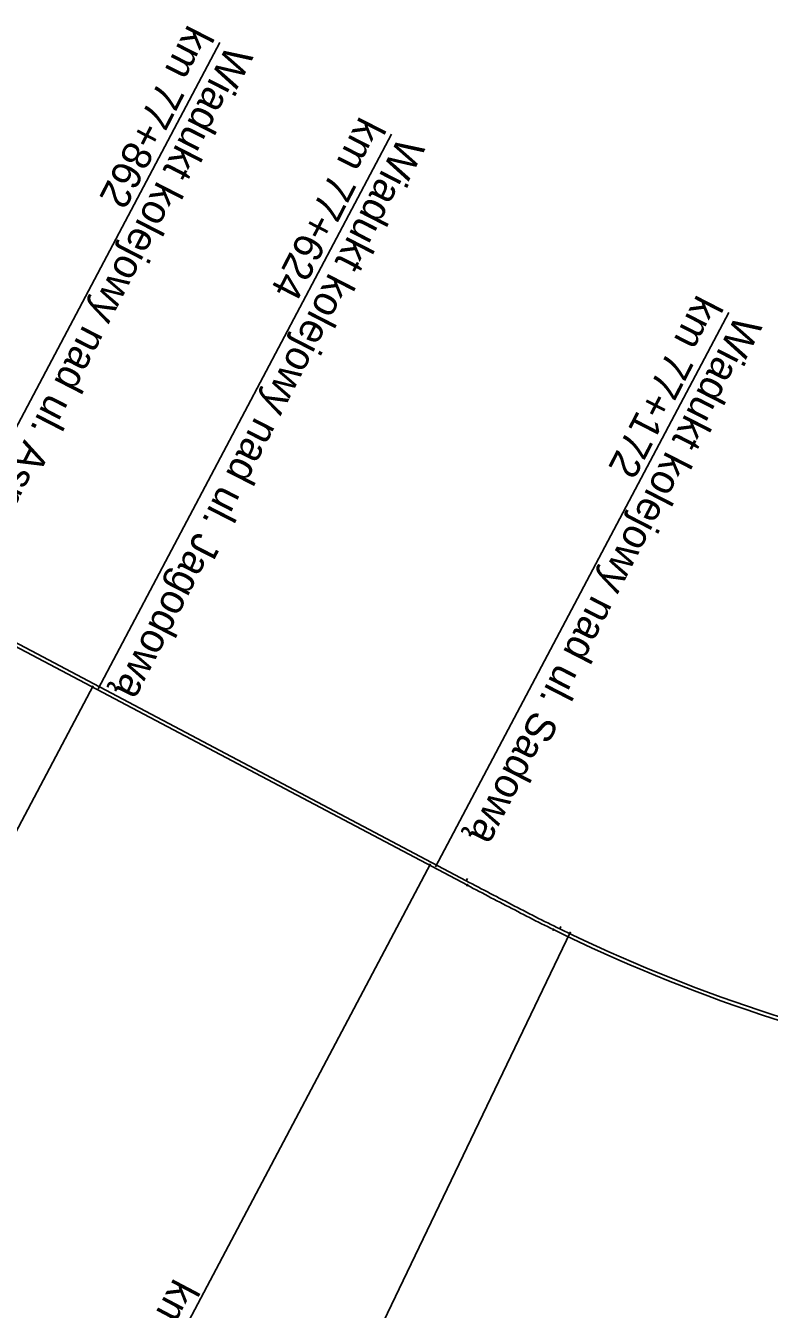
# Model space of a CAD drawing. Extents: x 6540402 to 6566579, y 5525343 to 5532423.
# Drawn here: x 6542041 to 6542924, y 5526352 to 5527877 of the extents above; entities that cross this region are included whole.
import ezdxf

# ---------------------------------------------------------------- set-up
doc = ezdxf.new("R2010")
doc.units = 0
for name, color, linetype in [('IR_ps_geometria', 7, 'Continuous'), ('TOR_PS_OPIS_T-hektometry projektowane', 7, 'Continuous'), ('TOR_PS_OPIS_T-opisy dodatkowe', 7, 'Continuous'), ('TOR_PS_OPIS_T-symbole geometrii', 7, 'Continuous'), ('TOR_PS_T-tory projektowane', 7, 'Continuous')]:
    doc.layers.add(name, color=color, linetype=linetype)

msp = doc.modelspace()

# ---------------------------------------------------------------- linework, layer by layer
at = {"layer": 'IR_ps_geometria'}
for points in [[(6542565.7, 5526856), (6542565.6, 5526855.8), (6542565.6, 5526855.8), (6542565.6, 5526855.8), (6542565.6, 5526855.8), (6542565.7, 5526855.7), (6542565.7, 5526855.7), (6542565.7, 5526855.7), (6542565.7, 5526855.6), (6542565.7, 5526855.6), (6542565.7, 5526855.6), (6542565.7, 5526855.5), (6542565.7, 5526855.5), (6542565.7, 5526855.5), (6542565.6, 5526855.5), (6542565.6, 5526855.4), (6542565.6, 5526855.4), (6542565.6, 5526855.4), (6542565.5, 5526855.4), (6542565.5, 5526855.4), (6542565.5, 5526855.4), (6542565.5, 5526855.4), (6542565.4, 5526855.4), (6542565.4, 5526855.4), (6542565.4, 5526855.4), (6542565.3, 5526855.4), (6542565.3, 5526855.4), (6542565.3, 5526855.4), (6542565.2, 5526855.4), (6542565.2, 5526855.5), (6542565.2, 5526855.5), (6542565.2, 5526855.5), (6542565.2, 5526855.6), (6542565.2, 5526855.6), (6542565.2, 5526855.6), (6542565.2, 5526855.7), (6542565.2, 5526855.7), (6542565.2, 5526855.7), (6542565.2, 5526855.7), (6542565.3, 5526855.8), (6542565.3, 5526855.8), (6542565.3, 5526855.8), (6542565.3, 5526855.8), (6542565.4, 5526855.8), (6542565.4, 5526855.8), (6542565.4, 5526855.9), (6542565.5, 5526855.9), (6542565.5, 5526855.8), (6542565.5, 5526855.8), (6542565.6, 5526855.8), (6542565.8, 5526856.3), (6542565.8, 5526856.3), (6542565.7, 5526856.3), (6542565.7, 5526856.3), (6542565.7, 5526856.4), (6542565.7, 5526856.4), (6542565.7, 5526856.4), (6542565.7, 5526856.4), (6542565.7, 5526856.5), (6542565.7, 5526856.5), (6542565.7, 5526856.5), (6542565.7, 5526856.6), (6542565.7, 5526856.6), (6542565.7, 5526856.6), (6542565.7, 5526856.7), (6542565.7, 5526856.7), (6542565.8, 5526856.7), (6542565.8, 5526856.7), (6542565.8, 5526856.7), (6542565.9, 5526856.7), (6542565.9, 5526856.7), (6542565.9, 5526856.7), (6542566, 5526856.7), (6542566, 5526856.7), (6542566, 5526856.7), (6542566.1, 5526856.7), (6542566.1, 5526856.7), (6542566.1, 5526856.6), (6542566.1, 5526856.6), (6542566.1, 5526856.6), (6542566.1, 5526856.6), (6542566.2, 5526856.5), (6542566.2, 5526856.5), (6542566.2, 5526856.5), (6542566.2, 5526856.4), (6542566.1, 5526856.4), (6542566.1, 5526856.4), (6542566.1, 5526856.3), (6542566.1, 5526856.3), (6542566.1, 5526856.3), (6542566, 5526856.3), (6542566, 5526856.3), (6542566, 5526856.2), (6542566, 5526856.2), (6542565.9, 5526856.2), (6542565.9, 5526856.2), (6542565.9, 5526856.2), (6542565.8, 5526856.3), (6542565.8, 5526856.3)], [(6542565.7, 5526856), (6542565.6, 5526855.8), (6542565.6, 5526855.8), (6542565.6, 5526855.8), (6542565.6, 5526855.8), (6542565.7, 5526855.7), (6542565.7, 5526855.7), (6542565.7, 5526855.7), (6542565.7, 5526855.6), (6542565.7, 5526855.6), (6542565.7, 5526855.6), (6542565.7, 5526855.5), (6542565.7, 5526855.5), (6542565.7, 5526855.5), (6542565.6, 5526855.5), (6542565.6, 5526855.4), (6542565.6, 5526855.4), (6542565.6, 5526855.4), (6542565.5, 5526855.4), (6542565.5, 5526855.4), (6542565.5, 5526855.4), (6542565.5, 5526855.4), (6542565.4, 5526855.4), (6542565.4, 5526855.4), (6542565.4, 5526855.4), (6542565.3, 5526855.4), (6542565.3, 5526855.4), (6542565.3, 5526855.4), (6542565.2, 5526855.4), (6542565.2, 5526855.5), (6542565.2, 5526855.5), (6542565.2, 5526855.5), (6542565.2, 5526855.6), (6542565.2, 5526855.6), (6542565.2, 5526855.6), (6542565.2, 5526855.7), (6542565.2, 5526855.7), (6542565.2, 5526855.7), (6542565.2, 5526855.7), (6542565.3, 5526855.8), (6542565.3, 5526855.8), (6542565.3, 5526855.8), (6542565.3, 5526855.8), (6542565.4, 5526855.8), (6542565.4, 5526855.8), (6542565.4, 5526855.9), (6542565.5, 5526855.9), (6542565.5, 5526855.8), (6542565.5, 5526855.8), (6542565.6, 5526855.8), (6542565.8, 5526856.3), (6542565.8, 5526856.3), (6542565.7, 5526856.3), (6542565.7, 5526856.3), (6542565.7, 5526856.4), (6542565.7, 5526856.4), (6542565.7, 5526856.4), (6542565.7, 5526856.4), (6542565.7, 5526856.5), (6542565.7, 5526856.5), (6542565.7, 5526856.5), (6542565.7, 5526856.6), (6542565.7, 5526856.6), (6542565.7, 5526856.6), (6542565.7, 5526856.7), (6542565.7, 5526856.7), (6542565.8, 5526856.7), (6542565.8, 5526856.7), (6542565.8, 5526856.7), (6542565.9, 5526856.7), (6542565.9, 5526856.7), (6542565.9, 5526856.7), (6542566, 5526856.7), (6542566, 5526856.7), (6542566, 5526856.7), (6542566.1, 5526856.7), (6542566.1, 5526856.7), (6542566.1, 5526856.6), (6542566.1, 5526856.6), (6542566.1, 5526856.6), (6542566.1, 5526856.6), (6542566.2, 5526856.5), (6542566.2, 5526856.5), (6542566.2, 5526856.5), (6542566.2, 5526856.4), (6542566.1, 5526856.4), (6542566.1, 5526856.4), (6542566.1, 5526856.3), (6542566.1, 5526856.3), (6542566.1, 5526856.3), (6542566, 5526856.3), (6542566, 5526856.3), (6542566, 5526856.2), (6542566, 5526856.2), (6542565.9, 5526856.2), (6542565.9, 5526856.2), (6542565.9, 5526856.2), (6542565.8, 5526856.3), (6542565.8, 5526856.3)], [(6542565.7, 5526856), (6542565.6, 5526855.8), (6542565.6, 5526855.8), (6542565.6, 5526855.8), (6542565.6, 5526855.8), (6542565.7, 5526855.7), (6542565.7, 5526855.7), (6542565.7, 5526855.7), (6542565.7, 5526855.6), (6542565.7, 5526855.6), (6542565.7, 5526855.6), (6542565.7, 5526855.5), (6542565.7, 5526855.5), (6542565.7, 5526855.5), (6542565.6, 5526855.5), (6542565.6, 5526855.4), (6542565.6, 5526855.4), (6542565.6, 5526855.4), (6542565.5, 5526855.4), (6542565.5, 5526855.4), (6542565.5, 5526855.4), (6542565.5, 5526855.4), (6542565.4, 5526855.4), (6542565.4, 5526855.4), (6542565.4, 5526855.4), (6542565.3, 5526855.4), (6542565.3, 5526855.4), (6542565.3, 5526855.4), (6542565.2, 5526855.4), (6542565.2, 5526855.5), (6542565.2, 5526855.5), (6542565.2, 5526855.5), (6542565.2, 5526855.6), (6542565.2, 5526855.6), (6542565.2, 5526855.6), (6542565.2, 5526855.7), (6542565.2, 5526855.7), (6542565.2, 5526855.7), (6542565.2, 5526855.7), (6542565.3, 5526855.8), (6542565.3, 5526855.8), (6542565.3, 5526855.8), (6542565.3, 5526855.8), (6542565.4, 5526855.8), (6542565.4, 5526855.8), (6542565.4, 5526855.9), (6542565.5, 5526855.9), (6542565.5, 5526855.8), (6542565.5, 5526855.8), (6542565.6, 5526855.8), (6542565.8, 5526856.3), (6542565.8, 5526856.3), (6542565.7, 5526856.3), (6542565.7, 5526856.3), (6542565.7, 5526856.4), (6542565.7, 5526856.4), (6542565.7, 5526856.4), (6542565.7, 5526856.4), (6542565.7, 5526856.5), (6542565.7, 5526856.5), (6542565.7, 5526856.5), (6542565.7, 5526856.6), (6542565.7, 5526856.6), (6542565.7, 5526856.6), (6542565.7, 5526856.7), (6542565.7, 5526856.7), (6542565.8, 5526856.7), (6542565.8, 5526856.7), (6542565.8, 5526856.7), (6542565.9, 5526856.7), (6542565.9, 5526856.7), (6542565.9, 5526856.7), (6542566, 5526856.7), (6542566, 5526856.7), (6542566, 5526856.7), (6542566.1, 5526856.7), (6542566.1, 5526856.7), (6542566.1, 5526856.6), (6542566.1, 5526856.6), (6542566.1, 5526856.6), (6542566.1, 5526856.6), (6542566.2, 5526856.5), (6542566.2, 5526856.5), (6542566.2, 5526856.5), (6542566.2, 5526856.4), (6542566.1, 5526856.4), (6542566.1, 5526856.4), (6542566.1, 5526856.3), (6542566.1, 5526856.3), (6542566.1, 5526856.3), (6542566, 5526856.3), (6542566, 5526856.3), (6542566, 5526856.2), (6542566, 5526856.2), (6542565.9, 5526856.2), (6542565.9, 5526856.2), (6542565.9, 5526856.2), (6542565.8, 5526856.3), (6542565.8, 5526856.3)], [(6542565.7, 5526856), (6542565.6, 5526855.8), (6542565.6, 5526855.8), (6542565.6, 5526855.8), (6542565.6, 5526855.8), (6542565.7, 5526855.7), (6542565.7, 5526855.7), (6542565.7, 5526855.7), (6542565.7, 5526855.6), (6542565.7, 5526855.6), (6542565.7, 5526855.6), (6542565.7, 5526855.5), (6542565.7, 5526855.5), (6542565.7, 5526855.5), (6542565.6, 5526855.5), (6542565.6, 5526855.4), (6542565.6, 5526855.4), (6542565.6, 5526855.4), (6542565.5, 5526855.4), (6542565.5, 5526855.4), (6542565.5, 5526855.4), (6542565.5, 5526855.4), (6542565.4, 5526855.4), (6542565.4, 5526855.4), (6542565.4, 5526855.4), (6542565.3, 5526855.4), (6542565.3, 5526855.4), (6542565.3, 5526855.4), (6542565.2, 5526855.4), (6542565.2, 5526855.5), (6542565.2, 5526855.5), (6542565.2, 5526855.5), (6542565.2, 5526855.6), (6542565.2, 5526855.6), (6542565.2, 5526855.6), (6542565.2, 5526855.7), (6542565.2, 5526855.7), (6542565.2, 5526855.7), (6542565.2, 5526855.7), (6542565.3, 5526855.8), (6542565.3, 5526855.8), (6542565.3, 5526855.8), (6542565.3, 5526855.8), (6542565.4, 5526855.8), (6542565.4, 5526855.8), (6542565.4, 5526855.9), (6542565.5, 5526855.9), (6542565.5, 5526855.8), (6542565.5, 5526855.8), (6542565.6, 5526855.8), (6542565.8, 5526856.3), (6542565.8, 5526856.3), (6542565.7, 5526856.3), (6542565.7, 5526856.3), (6542565.7, 5526856.4), (6542565.7, 5526856.4), (6542565.7, 5526856.4), (6542565.7, 5526856.4), (6542565.7, 5526856.5), (6542565.7, 5526856.5), (6542565.7, 5526856.5), (6542565.7, 5526856.6), (6542565.7, 5526856.6), (6542565.7, 5526856.6), (6542565.7, 5526856.7), (6542565.7, 5526856.7), (6542565.8, 5526856.7), (6542565.8, 5526856.7), (6542565.8, 5526856.7), (6542565.9, 5526856.7), (6542565.9, 5526856.7), (6542565.9, 5526856.7), (6542566, 5526856.7), (6542566, 5526856.7), (6542566, 5526856.7), (6542566.1, 5526856.7), (6542566.1, 5526856.7), (6542566.1, 5526856.6), (6542566.1, 5526856.6), (6542566.1, 5526856.6), (6542566.1, 5526856.6), (6542566.2, 5526856.5), (6542566.2, 5526856.5), (6542566.2, 5526856.5), (6542566.2, 5526856.4), (6542566.1, 5526856.4), (6542566.1, 5526856.4), (6542566.1, 5526856.3), (6542566.1, 5526856.3), (6542566.1, 5526856.3), (6542566, 5526856.3), (6542566, 5526856.3), (6542566, 5526856.2), (6542566, 5526856.2), (6542565.9, 5526856.2), (6542565.9, 5526856.2), (6542565.9, 5526856.2), (6542565.8, 5526856.3), (6542565.8, 5526856.3)], [(6542667.9, 5526803.3), (6542667.7, 5526803.1), (6542667.8, 5526803), (6542667.8, 5526803), (6542667.8, 5526803), (6542667.8, 5526803), (6542667.9, 5526803), (6542667.9, 5526802.9), (6542667.9, 5526802.9), (6542667.9, 5526802.9), (6542667.9, 5526802.8), (6542667.9, 5526802.8), (6542667.9, 5526802.8), (6542667.9, 5526802.7), (6542667.8, 5526802.7), (6542667.8, 5526802.7), (6542667.8, 5526802.7), (6542667.8, 5526802.6), (6542667.7, 5526802.6), (6542667.7, 5526802.6), (6542667.7, 5526802.6), (6542667.7, 5526802.6), (6542667.6, 5526802.6), (6542667.6, 5526802.6), (6542667.6, 5526802.6), (6542667.5, 5526802.6), (6542667.5, 5526802.6), (6542667.5, 5526802.7), (6542667.4, 5526802.7), (6542667.4, 5526802.7), (6542667.4, 5526802.7), (6542667.4, 5526802.8), (6542667.4, 5526802.8), (6542667.4, 5526802.8), (6542667.4, 5526802.9), (6542667.4, 5526802.9), (6542667.4, 5526802.9), (6542667.4, 5526803), (6542667.4, 5526803), (6542667.4, 5526803), (6542667.5, 5526803), (6542667.5, 5526803), (6542667.5, 5526803.1), (6542667.6, 5526803.1), (6542667.6, 5526803.1), (6542667.6, 5526803.1), (6542667.7, 5526803.1), (6542667.7, 5526803.1), (6542667.7, 5526803.1), (6542667.7, 5526803.1), (6542668, 5526803.5), (6542667.9, 5526803.5), (6542667.9, 5526803.6), (6542667.9, 5526803.6), (6542667.9, 5526803.6), (6542667.9, 5526803.6), (6542667.8, 5526803.7), (6542667.8, 5526803.7), (6542667.8, 5526803.7), (6542667.8, 5526803.8), (6542667.8, 5526803.8), (6542667.8, 5526803.8), (6542667.9, 5526803.8), (6542667.9, 5526803.9), (6542667.9, 5526803.9), (6542667.9, 5526803.9), (6542667.9, 5526803.9), (6542668, 5526804), (6542668, 5526804), (6542668, 5526804), (6542668.1, 5526804), (6542668.1, 5526804), (6542668.1, 5526804), (6542668.2, 5526804), (6542668.2, 5526804), (6542668.2, 5526803.9), (6542668.2, 5526803.9), (6542668.3, 5526803.9), (6542668.3, 5526803.9), (6542668.3, 5526803.8), (6542668.3, 5526803.8), (6542668.3, 5526803.8), (6542668.3, 5526803.8), (6542668.3, 5526803.7), (6542668.3, 5526803.7), (6542668.3, 5526803.7), (6542668.3, 5526803.6), (6542668.3, 5526803.6), (6542668.3, 5526803.6), (6542668.2, 5526803.6), (6542668.2, 5526803.5), (6542668.2, 5526803.5), (6542668.2, 5526803.5), (6542668.1, 5526803.5), (6542668.1, 5526803.5), (6542668.1, 5526803.5), (6542668, 5526803.5), (6542668, 5526803.5), (6542668, 5526803.5)], [(6542667.9, 5526803.3), (6542667.7, 5526803.1), (6542667.8, 5526803), (6542667.8, 5526803), (6542667.8, 5526803), (6542667.8, 5526803), (6542667.9, 5526803), (6542667.9, 5526802.9), (6542667.9, 5526802.9), (6542667.9, 5526802.9), (6542667.9, 5526802.8), (6542667.9, 5526802.8), (6542667.9, 5526802.8), (6542667.9, 5526802.7), (6542667.8, 5526802.7), (6542667.8, 5526802.7), (6542667.8, 5526802.7), (6542667.8, 5526802.6), (6542667.7, 5526802.6), (6542667.7, 5526802.6), (6542667.7, 5526802.6), (6542667.7, 5526802.6), (6542667.6, 5526802.6), (6542667.6, 5526802.6), (6542667.6, 5526802.6), (6542667.5, 5526802.6), (6542667.5, 5526802.6), (6542667.5, 5526802.7), (6542667.4, 5526802.7), (6542667.4, 5526802.7), (6542667.4, 5526802.7), (6542667.4, 5526802.8), (6542667.4, 5526802.8), (6542667.4, 5526802.8), (6542667.4, 5526802.9), (6542667.4, 5526802.9), (6542667.4, 5526802.9), (6542667.4, 5526803), (6542667.4, 5526803), (6542667.4, 5526803), (6542667.5, 5526803), (6542667.5, 5526803), (6542667.5, 5526803.1), (6542667.6, 5526803.1), (6542667.6, 5526803.1), (6542667.6, 5526803.1), (6542667.7, 5526803.1), (6542667.7, 5526803.1), (6542667.7, 5526803.1), (6542667.7, 5526803.1), (6542668, 5526803.5), (6542667.9, 5526803.5), (6542667.9, 5526803.6), (6542667.9, 5526803.6), (6542667.9, 5526803.6), (6542667.9, 5526803.6), (6542667.8, 5526803.7), (6542667.8, 5526803.7), (6542667.8, 5526803.7), (6542667.8, 5526803.8), (6542667.8, 5526803.8), (6542667.8, 5526803.8), (6542667.9, 5526803.8), (6542667.9, 5526803.9), (6542667.9, 5526803.9), (6542667.9, 5526803.9), (6542667.9, 5526803.9), (6542668, 5526804), (6542668, 5526804), (6542668, 5526804), (6542668.1, 5526804), (6542668.1, 5526804), (6542668.1, 5526804), (6542668.2, 5526804), (6542668.2, 5526804), (6542668.2, 5526803.9), (6542668.2, 5526803.9), (6542668.3, 5526803.9), (6542668.3, 5526803.9), (6542668.3, 5526803.8), (6542668.3, 5526803.8), (6542668.3, 5526803.8), (6542668.3, 5526803.8), (6542668.3, 5526803.7), (6542668.3, 5526803.7), (6542668.3, 5526803.7), (6542668.3, 5526803.6), (6542668.3, 5526803.6), (6542668.3, 5526803.6), (6542668.2, 5526803.6), (6542668.2, 5526803.5), (6542668.2, 5526803.5), (6542668.2, 5526803.5), (6542668.1, 5526803.5), (6542668.1, 5526803.5), (6542668.1, 5526803.5), (6542668, 5526803.5), (6542668, 5526803.5), (6542668, 5526803.5)], [(6542667.9, 5526803.3), (6542667.7, 5526803.1), (6542667.8, 5526803), (6542667.8, 5526803), (6542667.8, 5526803), (6542667.8, 5526803), (6542667.9, 5526803), (6542667.9, 5526802.9), (6542667.9, 5526802.9), (6542667.9, 5526802.9), (6542667.9, 5526802.8), (6542667.9, 5526802.8), (6542667.9, 5526802.8), (6542667.9, 5526802.7), (6542667.8, 5526802.7), (6542667.8, 5526802.7), (6542667.8, 5526802.7), (6542667.8, 5526802.6), (6542667.7, 5526802.6), (6542667.7, 5526802.6), (6542667.7, 5526802.6), (6542667.7, 5526802.6), (6542667.6, 5526802.6), (6542667.6, 5526802.6), (6542667.6, 5526802.6), (6542667.5, 5526802.6), (6542667.5, 5526802.6), (6542667.5, 5526802.7), (6542667.4, 5526802.7), (6542667.4, 5526802.7), (6542667.4, 5526802.7), (6542667.4, 5526802.8), (6542667.4, 5526802.8), (6542667.4, 5526802.8), (6542667.4, 5526802.9), (6542667.4, 5526802.9), (6542667.4, 5526802.9), (6542667.4, 5526803), (6542667.4, 5526803), (6542667.4, 5526803), (6542667.5, 5526803), (6542667.5, 5526803), (6542667.5, 5526803.1), (6542667.6, 5526803.1), (6542667.6, 5526803.1), (6542667.6, 5526803.1), (6542667.7, 5526803.1), (6542667.7, 5526803.1), (6542667.7, 5526803.1), (6542667.7, 5526803.1), (6542668, 5526803.5), (6542667.9, 5526803.5), (6542667.9, 5526803.6), (6542667.9, 5526803.6), (6542667.9, 5526803.6), (6542667.9, 5526803.6), (6542667.8, 5526803.7), (6542667.8, 5526803.7), (6542667.8, 5526803.7), (6542667.8, 5526803.8), (6542667.8, 5526803.8), (6542667.8, 5526803.8), (6542667.9, 5526803.8), (6542667.9, 5526803.9), (6542667.9, 5526803.9), (6542667.9, 5526803.9), (6542667.9, 5526803.9), (6542668, 5526804), (6542668, 5526804), (6542668, 5526804), (6542668.1, 5526804), (6542668.1, 5526804), (6542668.1, 5526804), (6542668.2, 5526804), (6542668.2, 5526804), (6542668.2, 5526803.9), (6542668.2, 5526803.9), (6542668.3, 5526803.9), (6542668.3, 5526803.9), (6542668.3, 5526803.8), (6542668.3, 5526803.8), (6542668.3, 5526803.8), (6542668.3, 5526803.8), (6542668.3, 5526803.7), (6542668.3, 5526803.7), (6542668.3, 5526803.7), (6542668.3, 5526803.6), (6542668.3, 5526803.6), (6542668.3, 5526803.6), (6542668.2, 5526803.6), (6542668.2, 5526803.5), (6542668.2, 5526803.5), (6542668.2, 5526803.5), (6542668.1, 5526803.5), (6542668.1, 5526803.5), (6542668.1, 5526803.5), (6542668, 5526803.5), (6542668, 5526803.5), (6542668, 5526803.5)], [(6542667.9, 5526803.3), (6542667.7, 5526803.1), (6542667.8, 5526803), (6542667.8, 5526803), (6542667.8, 5526803), (6542667.8, 5526803), (6542667.9, 5526803), (6542667.9, 5526802.9), (6542667.9, 5526802.9), (6542667.9, 5526802.9), (6542667.9, 5526802.8), (6542667.9, 5526802.8), (6542667.9, 5526802.8), (6542667.9, 5526802.7), (6542667.8, 5526802.7), (6542667.8, 5526802.7), (6542667.8, 5526802.7), (6542667.8, 5526802.6), (6542667.7, 5526802.6), (6542667.7, 5526802.6), (6542667.7, 5526802.6), (6542667.7, 5526802.6), (6542667.6, 5526802.6), (6542667.6, 5526802.6), (6542667.6, 5526802.6), (6542667.5, 5526802.6), (6542667.5, 5526802.6), (6542667.5, 5526802.7), (6542667.4, 5526802.7), (6542667.4, 5526802.7), (6542667.4, 5526802.7), (6542667.4, 5526802.8), (6542667.4, 5526802.8), (6542667.4, 5526802.8), (6542667.4, 5526802.9), (6542667.4, 5526802.9), (6542667.4, 5526802.9), (6542667.4, 5526803), (6542667.4, 5526803), (6542667.4, 5526803), (6542667.5, 5526803), (6542667.5, 5526803), (6542667.5, 5526803.1), (6542667.6, 5526803.1), (6542667.6, 5526803.1), (6542667.6, 5526803.1), (6542667.7, 5526803.1), (6542667.7, 5526803.1), (6542667.7, 5526803.1), (6542667.7, 5526803.1), (6542668, 5526803.5), (6542667.9, 5526803.5), (6542667.9, 5526803.6), (6542667.9, 5526803.6), (6542667.9, 5526803.6), (6542667.9, 5526803.6), (6542667.8, 5526803.7), (6542667.8, 5526803.7), (6542667.8, 5526803.7), (6542667.8, 5526803.8), (6542667.8, 5526803.8), (6542667.8, 5526803.8), (6542667.9, 5526803.8), (6542667.9, 5526803.9), (6542667.9, 5526803.9), (6542667.9, 5526803.9), (6542667.9, 5526803.9), (6542668, 5526804), (6542668, 5526804), (6542668, 5526804), (6542668.1, 5526804), (6542668.1, 5526804), (6542668.1, 5526804), (6542668.2, 5526804), (6542668.2, 5526804), (6542668.2, 5526803.9), (6542668.2, 5526803.9), (6542668.3, 5526803.9), (6542668.3, 5526803.9), (6542668.3, 5526803.8), (6542668.3, 5526803.8), (6542668.3, 5526803.8), (6542668.3, 5526803.8), (6542668.3, 5526803.7), (6542668.3, 5526803.7), (6542668.3, 5526803.7), (6542668.3, 5526803.6), (6542668.3, 5526803.6), (6542668.3, 5526803.6), (6542668.2, 5526803.6), (6542668.2, 5526803.5), (6542668.2, 5526803.5), (6542668.2, 5526803.5), (6542668.1, 5526803.5), (6542668.1, 5526803.5), (6542668.1, 5526803.5), (6542668, 5526803.5), (6542668, 5526803.5), (6542668, 5526803.5)]]:
    msp.add_lwpolyline(points, close=True, dxfattribs=at)
at = {"layer": 'TOR_PS_OPIS_T-hektometry projektowane'}
msp.add_lwpolyline([(6542688, 5526800.6), (6542357.2, 5526110.8)], dxfattribs=at)
at = {"layer": 'TOR_PS_OPIS_T-opisy dodatkowe'}
for p, q in [((6542271.8, 5527857.1), (6541923.5, 5527198.5)), ((6542475.8, 5527748.1), (6542127.5, 5527089.5)), ((6542876.1, 5527536.4), (6542527.9, 5526877.8)), ((6542121.3, 5527092.8), (6541773, 5526434.2)), ((6542521.8, 5526881.3), (6542173.6, 5526222.8))]:
    msp.add_line(p, q, dxfattribs=at)
at = {"layer": 'TOR_PS_OPIS_T-symbole geometrii'}
for p, q in [((6542564.4, 5526861.3), (6542565.8, 5526864)), ((6542564.4, 5526861.3), (6542564.4, 5526862.3)), ((6542564.4, 5526861.3), (6542565.2, 5526861.8)), ((6542675.5, 5526804.1), (6542676.8, 5526806.8)), ((6542675.5, 5526804.1), (6542675.5, 5526805.1)), ((6542675.5, 5526804.1), (6542676.4, 5526804.6))]:
    msp.add_line(p, q, dxfattribs=at)
at = {"layer": 'TOR_PS_T-tory projektowane'}
for p, q in [((6542564.4, 5526861.3), (6541343.1, 5527507.1)), ((6542565.7, 5526856), (6541344.1, 5527502))]:
    msp.add_line(p, q, dxfattribs=at)
for points in [[(6542675.5, 5526804.1), (6542671.9, 5526805.8), (6542668.3, 5526807.6), (6542664.7, 5526809.4), (6542661.1, 5526811.2), (6542657.4, 5526813), (6542653.8, 5526814.8), (6542650.2, 5526816.6), (6542646.6, 5526818.4), (6542643, 5526820.3), (6542639.5, 5526822.1), (6542635.9, 5526823.9), (6542632.3, 5526825.8), (6542628.7, 5526827.6), (6542625.1, 5526829.5), (6542621.5, 5526831.3), (6542617.9, 5526833.2), (6542614.4, 5526835), (6542610.8, 5526836.9), (6542607.2, 5526838.8), (6542603.6, 5526840.6), (6542600.1, 5526842.5), (6542596.5, 5526844.4), (6542592.9, 5526846.2), (6542589.4, 5526848.1), (6542585.8, 5526850), (6542582.2, 5526851.9), (6542578.7, 5526853.8), (6542575.1, 5526855.6), (6542571.5, 5526857.5), (6542568, 5526859.4), (6542564.4, 5526861.3)], [(6542667.9, 5526803.3), (6542664.3, 5526805), (6542660.7, 5526806.8), (6542657.2, 5526808.6), (6542653.6, 5526810.3), (6542650.1, 5526812.1), (6542646.6, 5526813.9), (6542643, 5526815.7), (6542639.5, 5526817.5), (6542636, 5526819.3), (6542632.4, 5526821.1), (6542628.9, 5526822.9), (6542625.4, 5526824.7), (6542621.9, 5526826.6), (6542618.3, 5526828.4), (6542614.8, 5526830.2), (6542611.3, 5526832), (6542607.8, 5526833.9), (6542604.3, 5526835.7), (6542600.8, 5526837.5), (6542597.2, 5526839.4), (6542593.7, 5526841.2), (6542590.2, 5526843.1), (6542586.7, 5526844.9), (6542583.2, 5526846.8), (6542579.7, 5526848.6), (6542576.2, 5526850.5), (6542572.7, 5526852.3), (6542569.2, 5526854.2), (6542565.7, 5526856)]]:
    msp.add_lwpolyline(points, dxfattribs=at)
for centre, radius, start, end in [((6543517.3, 5528529.7), 1920, 243.995, 259.2672), ((6543528.2, 5528553.2), 1950, 243.8194, 259.4428)]:
    msp.add_arc(centre, radius, start, end, dxfattribs=at)

# ---------------------------------------------------------------- texts
at = {"layer": 'TOR_PS_OPIS_T-opisy dodatkowe'}
for s, rotation, p in [('km 77+862', 242.8298, (6542234.2, 5527879.9)), ('Wiadukt kolejowy nad ul. Asnyka (boczna)', 242.8298, (6542280.9, 5527856)), ('km 77+624', 242.8298, (6542438.2, 5527770.9)), ('Wiadukt kolejowy nad ul. Jagodową', 242.8298, (6542484.9, 5527746.9)), ('km 77+172', 242.8298, (6542838.5, 5527559.2)), ('Wiadukt kolejowy nad ul. Sadową', 242.8298, (6542885.2, 5527535.2)), ('km 77+179', 242.1299, (6542217.6, 5526390.6))]:
    msp.add_text(s, height=35, rotation=rotation, dxfattribs=at).set_placement(p)

doc.saveas('drawing.dxf')
